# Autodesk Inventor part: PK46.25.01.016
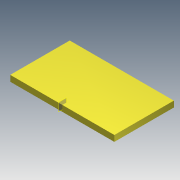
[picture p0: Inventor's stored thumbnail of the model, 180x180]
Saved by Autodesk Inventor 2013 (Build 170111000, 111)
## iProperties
Created: 2005-04
Part Number: PK46.25.01.016
Material: Steel, Mild
Document SubType Name: Modeling
Designer: salex
Manufacturer: Standard
Standards Organization: Custom
Density: 7.86 g/cm^3
Mass: 5634.05 g
Surface Area: 1036.8 cm^2
Volume: 716.8 cm^3
Author: salex
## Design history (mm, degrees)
sketch "Эскиз1"
  geometry: L1 (0, 0)-(280, 0); L2 (280, 0)-(280, 160); L3 (280, 160)-(0, 160); L4 (0, 160)-(0, 0)
  constraints: 8 end point, 2 parallel, 1 horizontal, 1 perpendicular, 1 other
  dimensions: "d0" = 160 distance of L3.end L1.start; "d1" = 280 distance of L1.start L1.end
extrude "Выдавливание1" new body sketch "Эскиз1" distance "d2" = 16; taper "d3" = 0 deg
node "РабПлоскость1"
body "Solid1"
